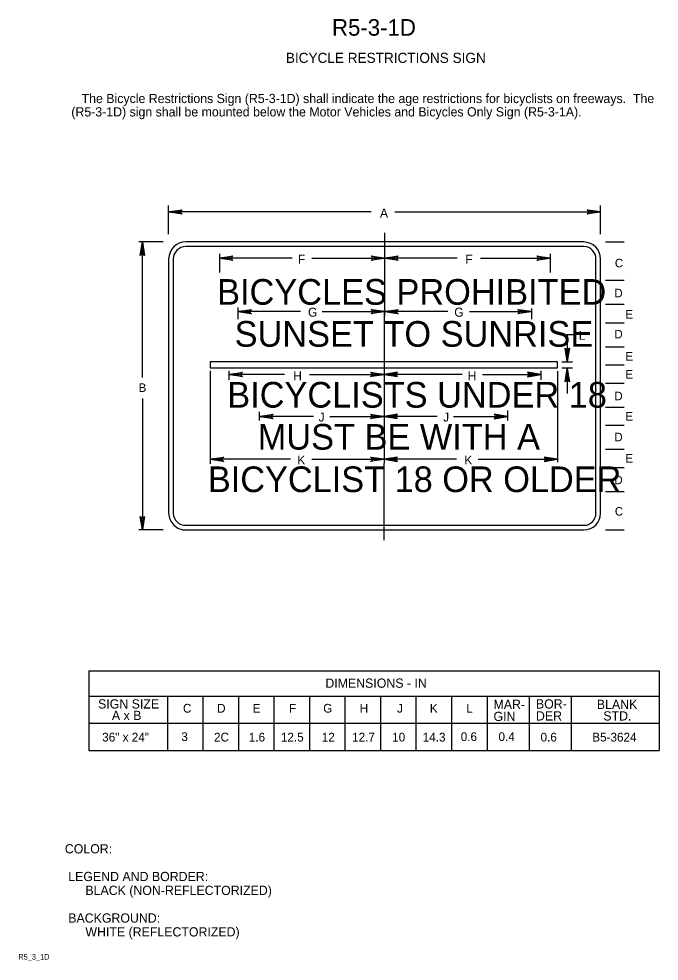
# Model space of a CAD drawing. Extents: x 0.013 to 0.186, y 0.004 to 0.259.
import ezdxf

# ---------------------------------------------------------------- set-up
doc = ezdxf.new("R2010")
doc.units = 0
for name, color, linetype in [('1', 7, 'Continuous'), ('12', 7, 'Continuous'), ('2', 7, 'Continuous'), ('3', 7, 'Continuous')]:
    doc.layers.add(name, color=color, linetype=linetype)

# ---------------------------------------------------------------- blocks, each defined once
blk = doc.blocks.new('RARROW')
at = {"layer": '3'}
for p, q in [((-2.156, 0.28500000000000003), (-2.2665, 0.384625)), ((-2.2665, 0.384625), (0, 0)), ((0, 0), (-2.2665, -0.379125)), ((-2.156, 0.28500000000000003), (-2.075625, 0.12075)), ((0, 0), (-2.156, 0.28500000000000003)), ((-2.14975, -0.2705), (0, 0)), ((-2.075625, 0.12075), (0, 0)), ((0, 0), (-2.074, -0.108)), ((-2.2665, -0.379125), (-2.14975, -0.2705)), ((-2.074, -0.108), (-2.14975, -0.2705))]:
    blk.add_line(p, q, dxfattribs=at)

msp = doc.modelspace()

# ---------------------------------------------------------------- linework, layer by layer
at = {"layer": '12'}
for p, q in [((0.16575, 0.19875), (0.057875, 0.19875)), ((0.05325, 0.194125), (0.05325, 0.12525)), ((0.17025, 0.12525), (0.17025, 0.194125)), ((0.0645, 0.16625), (0.0645, 0.164625)), ((0.15862500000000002, 0.16625), (0.0645, 0.16625)), ((0.15862500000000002, 0.164625), (0.15862500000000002, 0.16625)), ((0.0645, 0.164625), (0.15862500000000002, 0.164625)), ((0.057875, 0.12075), (0.16575, 0.12075))]:
    msp.add_line(p, q, dxfattribs=at)
for centre, radius, start, end in [((0.057884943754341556, 0.19411505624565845), 0.004634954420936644, 90.12292222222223, 179.87708055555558), ((0.16568749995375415, 0.19418749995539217), 0.004562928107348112, 359.21517500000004, 89.21517500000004), ((0.057834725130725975, 0.12533185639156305), 0.004585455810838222, 181.02285833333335, 271.0228583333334), ((0.16574999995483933, 0.1252500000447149), 0.0045000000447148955, 270, 0)]:
    msp.add_arc(centre, radius, start, end, dxfattribs=at)
at = {"layer": '3'}
for p, q in [((0.05325, 0.200875), (0.05325, 0.208625)), ((0.108125, 0.206875), (0.05325, 0.206875)), ((0.1145, 0.206875), (0.17025, 0.206875)), ((0.17025, 0.200875), (0.17025, 0.208625)), ((0.11175, 0.20125), (0.11158248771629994, 0.11799595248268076)), ((0.051750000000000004, 0.19875), (0.045125, 0.19875)), ((0.046125, 0.162), (0.046125, 0.19875)), ((0.16575, 0.1975), (0.057875, 0.1975)), ((0.171625, 0.19875), (0.176625, 0.19875)), ((0.0545, 0.194125), (0.0545, 0.12525)), ((0.067, 0.1955), (0.067, 0.1905)), ((0.08675000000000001, 0.194375), (0.067, 0.194375)), ((0.092, 0.194375), (0.11175, 0.194375)), ((0.094125, 0.194375), (0.11175, 0.194375)), ((0.11175, 0.1955), (0.11175, 0.193125)), ((0.131375, 0.194375), (0.11175, 0.194375)), ((0.13775, 0.194375), (0.15662500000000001, 0.194375)), ((0.15662500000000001, 0.1955), (0.15662500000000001, 0.1905)), ((0.169, 0.12525), (0.169, 0.194125)), ((0.171625, 0.18837500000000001), (0.176625, 0.18837500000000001)), ((0.171625, 0.181875), (0.176625, 0.181875)), ((0.07200000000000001, 0.181), (0.07200000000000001, 0.177875)), ((0.089, 0.179875), (0.07200000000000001, 0.179875)), ((0.094875, 0.179875), (0.11175, 0.179875)), ((0.11175, 0.181), (0.11175, 0.178625)), ((0.128875, 0.179875), (0.11175, 0.179875)), ((0.13475, 0.179875), (0.1515, 0.179875)), ((0.1515, 0.18075), (0.1515, 0.177875)), ((0.171625, 0.176875), (0.176625, 0.176875)), ((0.16125, 0.17366075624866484), (0.16125, 0.16625)), ((0.16125, 0.17366075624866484), (0.16325, 0.17366075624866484)), ((0.171625, 0.170375), (0.176625, 0.170375)), ((0.15975, 0.16625), (0.162625, 0.16625)), ((0.0645, 0.163875), (0.0645, 0.138625)), ((0.069625, 0.1614269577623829), (0.069625, 0.163875)), ((0.15411947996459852, 0.1614269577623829), (0.15411947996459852, 0.163875)), ((0.15862500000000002, 0.16375), (0.15862500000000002, 0.139125)), ((0.15975, 0.164625), (0.162625, 0.164625)), ((0.16125, 0.164625), (0.16125, 0.15775)), ((0.171625, 0.1655), (0.176625, 0.1655)), ((0.084625, 0.162875), (0.069625, 0.162875)), ((0.091375, 0.162875), (0.111625, 0.162875)), ((0.13275, 0.162875), (0.111625, 0.162875)), ((0.13825, 0.162875), (0.154125, 0.162875)), ((0.171625, 0.1605), (0.176625, 0.1605)), ((0.046125, 0.15637500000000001), (0.046125, 0.12075)), ((0.171625, 0.154), (0.176625, 0.154)), ((0.077875, 0.150375), (0.077875, 0.15275)), ((0.0925, 0.1515), (0.077875, 0.1515)), ((0.096875, 0.1515), (0.111625, 0.1515)), ((0.126, 0.1515), (0.111625, 0.1515)), ((0.130375, 0.1515), (0.145125, 0.1515)), ((0.145125, 0.150375), (0.145125, 0.153125)), ((0.171625, 0.149125), (0.176625, 0.149125)), ((0.171625, 0.142625), (0.176625, 0.142625)), ((0.08625000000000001, 0.139875), (0.0645, 0.139875)), ((0.092, 0.139875), (0.111625, 0.139875)), ((0.094125, 0.139875), (0.11175, 0.139875)), ((0.12925, 0.139875), (0.1115, 0.139875)), ((0.13125, 0.139875), (0.111625, 0.139875)), ((0.137125, 0.139875), (0.15862500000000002, 0.139875)), ((0.171625, 0.137625), (0.176625, 0.137625)), ((0.171625, 0.131125), (0.176625, 0.131125)), ((0.051750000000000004, 0.12075), (0.045125, 0.12075)), ((0.057875, 0.122), (0.16575, 0.122)), ((0.171625, 0.12075), (0.176625, 0.12075)), ((0.031625, 0.082625), (0.186125, 0.082625)), ((0.031625, 0.082625), (0.031625, 0.061)), ((0.186125, 0.082625), (0.186125, 0.061)), ((0.031625, 0.07575), (0.186125, 0.07575)), ((0.05291658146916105, 0.07574713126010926), (0.05291658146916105, 0.06099713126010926)), ((0.0625, 0.07575), (0.0625, 0.061)), ((0.072125, 0.07575), (0.072125, 0.061)), ((0.08175, 0.07575), (0.08175, 0.061)), ((0.091375, 0.07575), (0.091375, 0.061)), ((0.101, 0.07575), (0.101, 0.061)), ((0.110625, 0.07575), (0.110625, 0.061)), ((0.12025, 0.07575), (0.12025, 0.061)), ((0.129875, 0.07575), (0.129875, 0.061)), ((0.13954158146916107, 0.07574713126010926), (0.13954158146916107, 0.06099713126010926)), ((0.15091658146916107, 0.07574713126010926), (0.15091658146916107, 0.06099713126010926)), ((0.16229158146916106, 0.07574713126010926), (0.16229158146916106, 0.06099713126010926)), ((0.031625, 0.068375), (0.186125, 0.068375)), ((0.031625, 0.061), (0.186125, 0.061))]:
    msp.add_line(p, q, dxfattribs=at)
for centre, radius, start, end in [((0.057886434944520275, 0.19411356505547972), 0.0033864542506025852, 90.19346944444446, 179.80653055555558), ((0.16568749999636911, 0.19418749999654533), 0.0033130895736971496, 358.919075, 88.91907500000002), ((0.05783472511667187, 0.1253318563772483), 0.003335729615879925, 181.4061388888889, 271.4061388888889), ((0.165749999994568, 0.1252500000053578), 0.003250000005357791, 270, 0)]:
    msp.add_arc(centre, radius, start, end, dxfattribs=at)

# ---------------------------------------------------------------- block references
at = {"layer": '3', "xscale": 0.0016131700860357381}
for p, yscale, rotation in [((0.05325, 0.206875), 0.0015957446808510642, 180), ((0.046125, 0.19875), 0.0015957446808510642, 90), ((0.067, 0.194375), 0.0015957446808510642, 180), ((0.11175, 0.194375), 0.0015957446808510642, 180), ((0.07200000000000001, 0.179875), 0.0015957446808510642, 180), ((0.11175, 0.179875), 0.0015957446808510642, 180), ((0.16125, 0.166375), 0.0015957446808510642, -90), ((0.069625, 0.162875), 0.0015957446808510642, 180), ((0.111625, 0.162875), -0.0015957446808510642, 180), ((0.16125, 0.1645), 0.0015957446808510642, 90), ((0.077875, 0.1515), 0.0015957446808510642, 180), ((0.111625, 0.1515), -0.0015957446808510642, 180), ((0.0645, 0.139875), 0.0015957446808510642, 180), ((0.111625, 0.139875), -0.0015957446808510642, 180), ((0.046125, 0.12075), 0.0015957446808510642, -90)]:
    msp.add_blockref('RARROW', p, dxfattribs=dict(at, yscale=yscale, rotation=rotation))
for p, yscale in [((0.17025, 0.206875), 0.0015957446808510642), ((0.11175, 0.194375), 0.0015957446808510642), ((0.15662500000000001, 0.194375), 0.0015957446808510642), ((0.11175, 0.179875), 0.0015957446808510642), ((0.1515, 0.179875), 0.0015957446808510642), ((0.111625, 0.162875), 0.0015957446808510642), ((0.154125, 0.162875), -0.0015957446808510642), ((0.111625, 0.1515), 0.0015957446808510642), ((0.145125, 0.1515), -0.0015957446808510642), ((0.111625, 0.139875), 0.0015957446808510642), ((0.15862500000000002, 0.139875), -0.0015957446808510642)]:
    msp.add_blockref('RARROW', p, dxfattribs=dict(at, yscale=yscale))

# ---------------------------------------------------------------- texts
at = {"layer": '1'}
for s, height, p in [('R5-3-1D', 0.0045000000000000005, (0.0975, 0.254625)), ('BICYCLE RESTRICTIONS SIGN', 0.00275025, (0.085, 0.24725)), ('COLOR:', 0.0024997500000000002, (0.025125, 0.033125)), (' LEGEND AND BORDER:', 0.0024997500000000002, (0.025125, 0.025625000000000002)), ('      BLACK (NON-REFLECTORIZED)', 0.0024997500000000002, (0.025125, 0.021875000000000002)), (' BACKGROUND:', 0.0024997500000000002, (0.025125, 0.014375)), ('      WHITE (REFLECTORIZED)', 0.0024997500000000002, (0.025125, 0.010625)), ('R5_3_1D', 0.0015, (0.0125, 0.004375))]:
    msp.add_text(s, height=height, dxfattribs=at).set_placement(p)
at = {"layer": '12'}
for s, height, p in [('BICYCLES PROHIBITED', 0.00695475, (0.066375, 0.18175)), ('SUNSET TO SUNRISE', 0.00695475, (0.07112500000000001, 0.170375)), ('BICYCLISTS UNDER 18', 0.00695475, (0.069125, 0.153875)), ('MUST BE WITH A', 0.00695475, (0.077375, 0.14250000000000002)), ('BICYCLIST 18 OR OLDER', 0.0069465, (0.063875, 0.131))]:
    msp.add_text(s, height=height, dxfattribs=at).set_placement(p)
at = {"layer": '2'}
for s, p in [('   The Bicycle Restrictions Sign (R5-3-1D) shall indicate the age restrictions for bicyclists on freeways.  The', (0.026875, 0.236375)), ('(R5-3-1D) sign shall be mounted below the Motor Vehicles and Bicycles Only Sign (R5-3-1A).', (0.026875, 0.23275))]:
    msp.add_text(s, height=0.0024997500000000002, dxfattribs=at).set_placement(p)
at = {"layer": '3'}
for s, height, p in [('A', 0.00243675, (0.1105, 0.205375)), ('F', 0.00243675, (0.08825, 0.192875)), ('F', 0.00243675, (0.133625, 0.192875)), ('C', 0.0023152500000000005, (0.174125, 0.19187500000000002)), ('D', 0.0023152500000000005, (0.17400000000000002, 0.18375)), ('G', 0.00243675, (0.091, 0.1785)), ('G', 0.00243675, (0.130625, 0.1785)), ('E', 0.0023152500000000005, (0.177, 0.178)), ('L', 0.0023752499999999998, (0.164375, 0.17225000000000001)), ('D', 0.0023152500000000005, (0.17400000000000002, 0.172625)), ('E', 0.0023152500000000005, (0.177, 0.166625)), ('H', 0.00243675, (0.08700000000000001, 0.16125)), ('H', 0.00243675, (0.13425, 0.16125)), ('E', 0.0023152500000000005, (0.177, 0.16175)), ('B', 0.0023152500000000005, (0.045125, 0.15812500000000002)), ('D', 0.0023152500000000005, (0.17400000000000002, 0.155875)), ('J', 0.0023752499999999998, (0.093875, 0.150125)), ('J', 0.0023752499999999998, (0.12762500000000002, 0.150125)), ('E', 0.0023152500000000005, (0.177, 0.150375)), ('D', 0.0023152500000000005, (0.17400000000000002, 0.14475)), ('K', 0.0023752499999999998, (0.088125, 0.1385)), ('K', 0.0023752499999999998, (0.133375, 0.1385)), ('E', 0.0023152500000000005, (0.177, 0.139)), ('D', 0.0023152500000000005, (0.17400000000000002, 0.133125)), ('C', 0.0023152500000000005, (0.174125, 0.124625)), ('DIMENSIONS - IN', 0.0024997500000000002, (0.09570061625, 0.078)), ('SIGN SIZE', 0.0024997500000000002, (0.034125, 0.072375)), ('MAR-', 0.0024997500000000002, (0.14125000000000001, 0.07225)), ('BOR-', 0.0024997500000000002, (0.15275, 0.072375)), ('BLANK', 0.0024997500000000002, (0.16925, 0.07225)), ('A x B', 0.0024997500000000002, (0.037875, 0.06925)), ('C', 0.0023752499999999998, (0.057125, 0.07125000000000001)), ('D', 0.0023752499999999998, (0.066375, 0.07125000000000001)), ('E', 0.0023752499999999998, (0.076, 0.07125000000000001)), ('F', 0.0023752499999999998, (0.085875, 0.07125000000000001)), ('G', 0.0023752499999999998, (0.095125, 0.07125000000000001)), ('H', 0.0023752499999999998, (0.105, 0.07125000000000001)), ('J', 0.0023752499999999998, (0.115125, 0.07125000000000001)), ('K', 0.0023752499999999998, (0.124, 0.07125000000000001)), ('L', 0.0023752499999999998, (0.133875, 0.07125000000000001)), ('GIN', 0.0024997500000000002, (0.14125000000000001, 0.069)), ('DER', 0.0024997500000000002, (0.15275, 0.069125)), ('STD.', 0.0024997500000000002, (0.171, 0.069125)), ('36" x 24"', 0.0023752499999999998, (0.035245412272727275, 0.063437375)), ('3', 0.0023752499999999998, (0.05668161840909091, 0.063562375)), ('2C', 0.0023752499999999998, (0.06553957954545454, 0.063437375)), ('1.6', 0.0023752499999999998, (0.07495944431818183, 0.063437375)), ('12.5', 0.0023752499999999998, (0.08365161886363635, 0.063437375)), ('12', 0.0023752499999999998, (0.09472876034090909, 0.063437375)), ('12.7', 0.0023752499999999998, (0.10293436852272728, 0.063437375)), ('10', 0.0023752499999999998, (0.11379725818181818, 0.063437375)), ('14.3', 0.0023752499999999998, (0.12205828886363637, 0.063437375)), ('0.6', 0.0023752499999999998, (0.1323685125, 0.063562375)), ('0.4', 0.0023752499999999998, (0.14260699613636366, 0.063562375)), ('0.6', 0.0023752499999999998, (0.1539935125, 0.063437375)), ('B5-3624', 0.0023752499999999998, (0.167993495, 0.063437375))]:
    msp.add_text(s, height=height, dxfattribs=at).set_placement(p)

doc.saveas('drawing.dxf')
